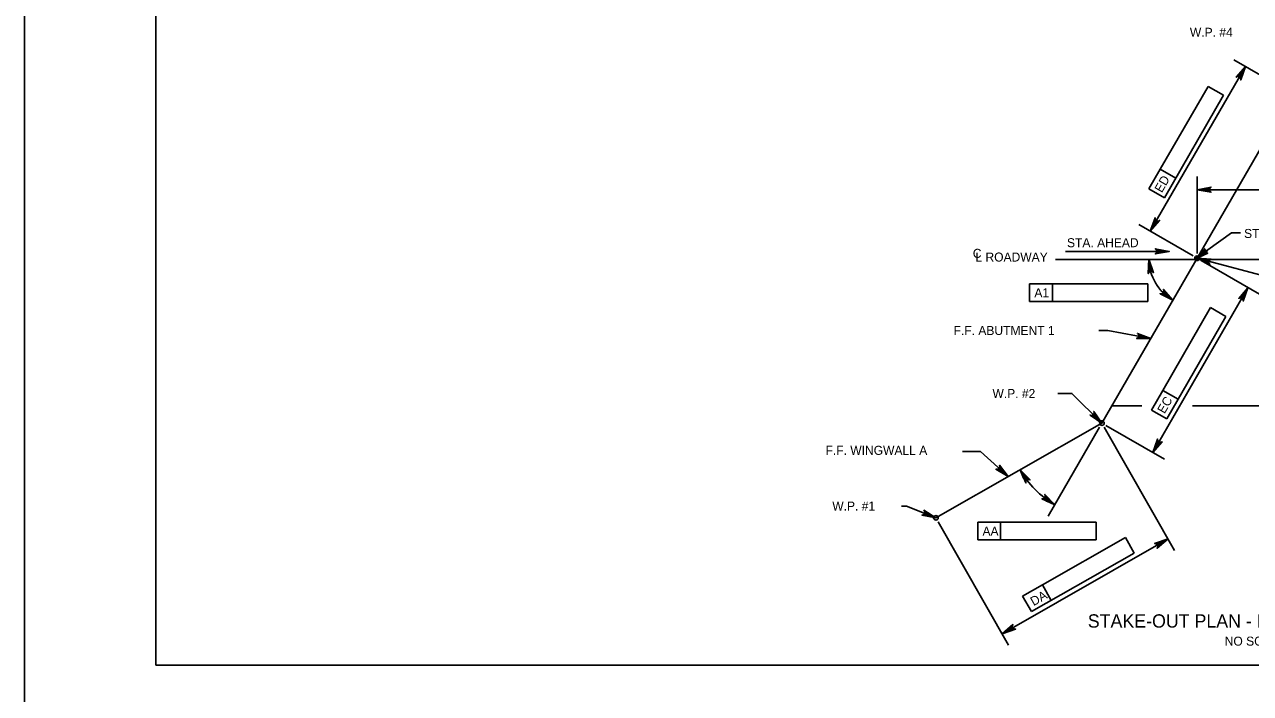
# Model space of a CAD drawing. Extents: x 0 to 36.3, y -66 to 0.
# Drawn here: x 0 to 16.33, y -43.62 to -34.72 of the extents above; entities that cross this region are included whole.
import ezdxf

# ---------------------------------------------------------------- set-up
doc = ezdxf.new("R2010")
doc.units = 0
for name, color, linetype in [('1', 7, 'Continuous'), ('2', 7, 'Continuous'), ('3', 7, 'Continuous'), ('4', 7, 'Continuous'), ('5', 7, 'Continuous'), ('63', 7, 'Continuous')]:
    doc.layers.add(name, color=color, linetype=linetype)

msp = doc.modelspace()

# ---------------------------------------------------------------- linework, layer by layer
at = {"layer": '1'}
msp.add_lwpolyline([(1.75, -43.25), (33.25, -43.25), (33.25, -22.75), (1.75, -22.75)], close=True, dxfattribs=at)
at = {"layer": '2'}
for p, q in [((16.888, -35.633), (14.353, -40.024)), ((14.485, -39.795), (14.886, -39.795)), ((15.559, -39.795), (21.181, -39.795)), ((14.353, -40.024), (12.142, -41.286))]:
    msp.add_line(p, q, dxfattribs=at)
at = {"layer": '3'}
msp.add_line((13.733, -37.844), (19.272, -37.844), dxfattribs=at)
for centre in [(15.621, -37.829), (14.353, -40.024), (12.142, -41.286)]:
    msp.add_circle(centre, 0.0304, dxfattribs=at)
at = {"layer": '4'}
for p, q in [((16.265, -35.274), (14.998, -37.469)), ((16.835, -35.603), (16.112, -35.185)), ((15.131, -36.643), (15.767, -35.541)), ((15.767, -35.541), (15.972, -35.659)), ((15.185, -37.023), (15.972, -35.659)), ((14.98, -36.904), (15.131, -36.643)), ((15.131, -36.643), (15.336, -36.761)), ((15.621, -37.767), (15.622, -36.739)), ((14.98, -36.904), (15.185, -37.023)), ((15.622, -36.916), (22.312, -36.916)), ((15.567, -37.798), (14.844, -37.38)), ((15.592, -37.84), (16.078, -37.492)), ((16.078, -37.492), (16.198, -37.492)), ((15.249, -37.737), (13.868, -37.737)), ((15.674, -37.859), (16.453, -38.309)), ((13.39, -38.17), (13.693, -38.17)), ((13.39, -38.17), (13.39, -38.406)), ((13.693, -38.17), (13.693, -38.406)), ((13.693, -38.17), (14.965, -38.17)), ((14.965, -38.17), (14.965, -38.406)), ((16.299, -38.221), (15.032, -40.416)), ((13.39, -38.406), (14.965, -38.406)), ((15.165, -39.589), (15.801, -38.487)), ((15.801, -38.487), (16.006, -38.605)), ((15.219, -39.969), (16.006, -38.605)), ((14.431, -38.791), (14.311, -38.791)), ((15.004, -38.897), (14.431, -38.791)), ((15.014, -39.851), (15.165, -39.589)), ((15.165, -39.589), (15.37, -39.707)), ((15.014, -39.851), (15.219, -39.969)), ((14.322, -40.077), (13.637, -41.264)), ((14.384, -40.077), (15.322, -41.721)), ((14.406, -40.055), (15.185, -40.504)), ((12.172, -41.339), (13.11, -42.983)), ((12.7, -41.343), (13.002, -41.343)), ((12.7, -41.343), (12.7, -41.579)), ((13.002, -41.343), (13.002, -41.579)), ((13.002, -41.343), (14.275, -41.343)), ((14.275, -41.343), (14.275, -41.579)), ((12.7, -41.579), (14.275, -41.579)), ((13.023, -42.829), (15.234, -41.567)), ((13.56, -42.18), (14.665, -41.55)), ((14.665, -41.55), (14.782, -41.755)), ((13.414, -42.535), (14.782, -41.755)), ((13.297, -42.33), (13.56, -42.18)), ((13.56, -42.18), (13.677, -42.385)), ((13.297, -42.33), (13.414, -42.535))]:
    msp.add_line(p, q, dxfattribs=at)
for points in [[(16.189, -35.366), (16.223, -35.386), (16.265, -35.274)], [(15.74, -36.897), (15.74, -36.936), (15.622, -36.916)], [(15.04, -37.357), (15.074, -37.377), (14.998, -37.469)], [(15.753, -37.749), (15.73, -37.717), (15.644, -37.803)], [(15.621, -37.829), (15.732, -37.869), (15.737, -37.85)], [(16.223, -38.313), (16.257, -38.333), (16.299, -38.221)], [(14.353, -40.024), (14.276, -39.934), (14.262, -39.948)], [(15.074, -40.304), (15.108, -40.323), (15.032, -40.416)], [(13.103, -40.737), (13.022, -40.651), (13.009, -40.665)], [(13.31, -40.756), (13.343, -40.735), (13.264, -40.646)], [(13.637, -41.03), (13.616, -41.063), (13.726, -41.11)], [(12.142, -41.286), (12.036, -41.233), (12.028, -41.251)], [(15.122, -41.609), (15.141, -41.643), (15.234, -41.567)], [(13.115, -42.754), (13.135, -42.788), (13.023, -42.829)]]:
    msp.add_lwpolyline(points, close=True, dxfattribs=at)
for points in [[(15.249, -37.737), (15.063, -37.772), (15.077, -37.762), (15.084, -37.75), (15.087, -37.737), (15.084, -37.725), (15.077, -37.712), (15.063, -37.703), (15.249, -37.737), (15.077, -37.712), (15.084, -37.725), (15.249, -37.737), (15.087, -37.737), (15.084, -37.75), (15.249, -37.737), (15.077, -37.762)], [(14.976, -37.843), (15.039, -38.022), (15.027, -38.009), (15.014, -38.004), (15.001, -38.004), (14.989, -38.008), (14.978, -38.017), (14.97, -38.033), (14.976, -37.843), (14.978, -38.017), (14.989, -38.008), (14.976, -37.843), (15.001, -38.004), (15.014, -38.004), (14.976, -37.843), (15.027, -38.009)], [(15.621, -37.829), (16.693, -38.114), (16.784, -38.114)], [(15.298, -38.387), (15.129, -38.301), (15.147, -38.301), (15.16, -38.296), (15.17, -38.288), (15.176, -38.276), (15.177, -38.262), (15.172, -38.245), (15.298, -38.387), (15.177, -38.262), (15.176, -38.276), (15.298, -38.387), (15.17, -38.288), (15.16, -38.296), (15.298, -38.387), (15.147, -38.301)], [(16.299, -38.221), (16.236, -38.399), (16.235, -38.382), (16.228, -38.369), (16.218, -38.361), (16.206, -38.357), (16.192, -38.357), (16.176, -38.364), (16.299, -38.221), (16.192, -38.357), (16.206, -38.357), (16.299, -38.221), (16.218, -38.361), (16.228, -38.369), (16.299, -38.221), (16.235, -38.382)], [(15.004, -38.897), (14.814, -38.897), (14.83, -38.89), (14.84, -38.879), (14.844, -38.867), (14.844, -38.855), (14.839, -38.841), (14.827, -38.829), (15.004, -38.897), (14.839, -38.841), (14.844, -38.855), (15.004, -38.897), (14.844, -38.867), (14.84, -38.879), (15.004, -38.897), (14.83, -38.89)], [(14.353, -40.024), (13.954, -39.63), (13.765, -39.63)], [(14.353, -40.024), (14.196, -39.918), (14.213, -39.921), (14.227, -39.917), (14.238, -39.91), (14.245, -39.899), (14.248, -39.885), (14.245, -39.868), (14.353, -40.024), (14.248, -39.885), (14.245, -39.899), (14.353, -40.024), (14.238, -39.91), (14.227, -39.917), (14.353, -40.024), (14.213, -39.921)], [(15.032, -40.416), (15.095, -40.237), (15.096, -40.254), (15.103, -40.267), (15.113, -40.275), (15.125, -40.279), (15.14, -40.279), (15.155, -40.272), (15.032, -40.416), (15.14, -40.279), (15.125, -40.279), (15.032, -40.416), (15.113, -40.275), (15.103, -40.267), (15.032, -40.416), (15.096, -40.254)], [(13.103, -40.737), (12.737, -40.404)], [(13.103, -40.737), (12.941, -40.638), (12.959, -40.64), (12.973, -40.636), (12.983, -40.628), (12.989, -40.617), (12.992, -40.603), (12.989, -40.586), (13.103, -40.737), (12.992, -40.603), (12.989, -40.617), (13.103, -40.737), (12.983, -40.628), (12.973, -40.636), (13.103, -40.737), (12.959, -40.64)], [(13.264, -40.646), (13.397, -40.78), (13.381, -40.774), (13.367, -40.775), (13.355, -40.78), (13.346, -40.789), (13.34, -40.802), (13.34, -40.82), (13.264, -40.646), (13.34, -40.802), (13.346, -40.789), (13.264, -40.646), (13.355, -40.78), (13.367, -40.775), (13.264, -40.646), (13.381, -40.774)], [(13.725, -41.112), (13.553, -41.032), (13.57, -41.033), (13.584, -41.027), (13.593, -41.018), (13.598, -41.006), (13.599, -40.992), (13.593, -40.975), (13.725, -41.112), (13.599, -40.992), (13.598, -41.006), (13.725, -41.112), (13.593, -41.018), (13.584, -41.027), (13.725, -41.112), (13.57, -41.033)], [(12.142, -41.286), (11.748, -41.129), (11.683, -41.129)], [(12.142, -41.286), (11.956, -41.249), (11.973, -41.245), (11.984, -41.237), (11.991, -41.226), (11.993, -41.213), (11.991, -41.199), (11.981, -41.184), (12.142, -41.286), (11.991, -41.199), (11.993, -41.213), (12.142, -41.286), (11.991, -41.226), (11.984, -41.237), (12.142, -41.286), (11.973, -41.245)], [(15.234, -41.567), (15.089, -41.69), (15.097, -41.674), (15.097, -41.66), (15.093, -41.648), (15.085, -41.638), (15.072, -41.631), (15.055, -41.629), (15.234, -41.567), (15.072, -41.631), (15.085, -41.638), (15.234, -41.567), (15.093, -41.648), (15.097, -41.66), (15.234, -41.567), (15.097, -41.674)], [(13.023, -42.829), (13.167, -42.707), (13.16, -42.722), (13.159, -42.737), (13.164, -42.749), (13.172, -42.759), (13.184, -42.766), (13.202, -42.767), (13.023, -42.829), (13.184, -42.766), (13.172, -42.759), (13.023, -42.829), (13.164, -42.749), (13.159, -42.737), (13.023, -42.829), (13.16, -42.722)]]:
    msp.add_lwpolyline(points, dxfattribs=at)
for centre, radius, start, end in [((15.621, -37.829), 0.644, 181.3505, 240), ((14.353, -40.024), 1.255, 209.7121, 239.9991)]:
    msp.add_arc(centre, radius, start, end, dxfattribs=at)
at = {"layer": '5'}
msp.add_line((12.737, -40.404), (12.496, -40.404), dxfattribs=at)
for points in [[(16.265, -35.274), (16.202, -35.453), (16.201, -35.435), (16.194, -35.423), (16.184, -35.415), (16.172, -35.41), (16.157, -35.41), (16.142, -35.418), (16.265, -35.274), (16.157, -35.41), (16.172, -35.41), (16.265, -35.274), (16.184, -35.415), (16.194, -35.423), (16.265, -35.274), (16.201, -35.435)], [(15.622, -36.916), (15.808, -36.882), (15.794, -36.892), (15.787, -36.904), (15.785, -36.916), (15.787, -36.929), (15.794, -36.941), (15.808, -36.951), (15.622, -36.916), (15.794, -36.941), (15.787, -36.929), (15.622, -36.916), (15.785, -36.916), (15.787, -36.904), (15.622, -36.916), (15.794, -36.892)], [(14.998, -37.469), (15.061, -37.29), (15.062, -37.308), (15.069, -37.32), (15.079, -37.328), (15.091, -37.333), (15.105, -37.333), (15.121, -37.325), (14.998, -37.469), (15.105, -37.333), (15.091, -37.333), (14.998, -37.469), (15.079, -37.328), (15.069, -37.32), (14.998, -37.469), (15.062, -37.308)], [(15.592, -37.84), (15.724, -37.703), (15.718, -37.719), (15.719, -37.734), (15.724, -37.745), (15.733, -37.754), (15.747, -37.76), (15.764, -37.76), (15.592, -37.84), (15.747, -37.76), (15.733, -37.754), (15.592, -37.84), (15.724, -37.745), (15.719, -37.734), (15.592, -37.84), (15.718, -37.719)], [(15.621, -37.829), (15.81, -37.843), (15.793, -37.849), (15.783, -37.859), (15.778, -37.87), (15.776, -37.883), (15.78, -37.897), (15.792, -37.91), (15.621, -37.829), (15.78, -37.897), (15.776, -37.883), (15.621, -37.829), (15.778, -37.87), (15.783, -37.859), (15.621, -37.829), (15.793, -37.849)]]:
    msp.add_lwpolyline(points, dxfattribs=at)
at = {"layer": '63'}
msp.add_lwpolyline([(0, -44), (34, -44), (34, -22), (0, -22)], close=True, dxfattribs=at)

# ---------------------------------------------------------------- texts
at = {"layer": '4'}
for s, height, p in [('W.P. #4', 0.12, (15.525, -34.88)), ('STA. AHEAD', 0.12, (13.888, -37.682)), ('STA.', 0.12, (16.247, -37.559)), ('C', 0.12, (12.633, -37.824)), ('L ROADWAY', 0.12, (12.668, -37.873)), ('A1', 0.12, (13.453, -38.348)), ('F.F. ABUTMENT 1', 0.12, (12.377, -38.851)), ('W.P. #2', 0.12, (12.895, -39.69)), ('F.F. WINGWALL A', 0.12, (10.671, -40.447)), ('W.P. #1', 0.12, (10.761, -41.189)), ('AA', 0.12, (12.762, -41.524)), ('STAKE-OUT PLAN - LEFT SKEW', 0.17717, (14.165, -42.748)), ('NO SCALE', 0.12, (15.989, -42.988))]:
    msp.add_text(s, height=height, dxfattribs=at).set_placement(p)
for s, rotation, p in [('ED', 60, (15.151, -36.965)), ('EC', 60, (15.187, -39.908)), ('DA', 29.7109, (13.443, -42.463))]:
    msp.add_text(s, height=0.12, rotation=rotation, dxfattribs=at).set_placement(p)

doc.saveas('drawing.dxf')
